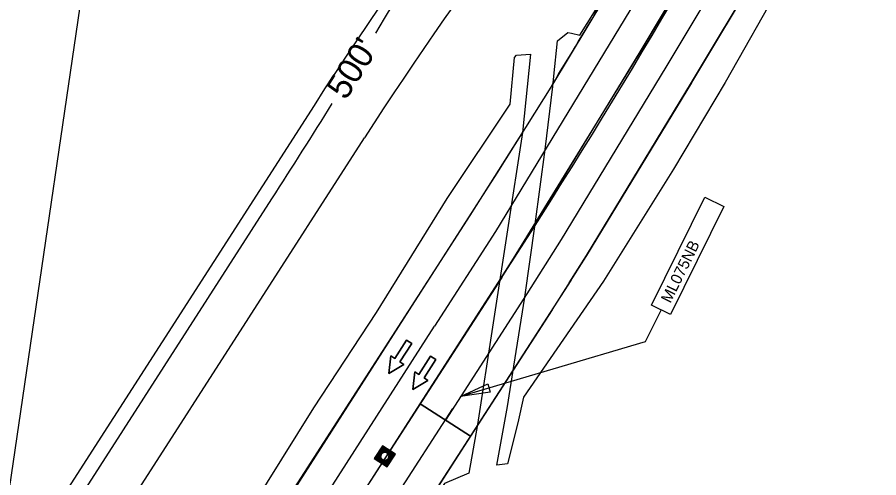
# Model space of a CAD drawing. Extents: x 14104283 to 14128447, y 8633203 to 8671666.
# Drawn here: x 14119316 to 14119660.6, y 8669344.5 to 8669528.4 of the extents above; entities that cross this region are included whole.
import ezdxf

# ---------------------------------------------------------------- set-up
doc = ezdxf.new("R2010")
doc.units = 0
for name, color, linetype in [('dsnCellElements', 7, 'Continuous'), ('dsnNonPlotable', 7, 'Continuous'), ('dsnPaintExistingBrokenLaneLineWhite', 7, 'Continuous'), ('dsnPaintExistingDoubleCenterYellow', 7, 'Continuous'), ('dsnPaintExistingEdgeLineRightWhite', 7, 'Continuous'), ('dsnPaintPlaceBrokenLineWhite', 7, 'Continuous'), ('dsnShadingPaved', 7, 'Continuous'), ('dsnStdLabel', 7, 'Continuous'), ('dsnStgShadingPrevPav', 7, 'Continuous'), ('dsnStgShadingPropPav', 7, 'Continuous'), ('Level 2', 7, 'Continuous'), ('Level 5', 7, 'Continuous'), ('Text', 7, 'Continuous')]:
    doc.layers.add(name, color=color, linetype=linetype)

msp = doc.modelspace()

# ---------------------------------------------------------------- linework, layer by layer
at = {"layer": 'dsnCellElements'}
msp.add_circle((14119463.04, 8669353.02), 1.65, dxfattribs=at)
at = {"layer": 'dsnNonPlotable'}
msp.add_lwpolyline([(14118774.15, 8669147.84), (14119001.66, 8670698.74), (14119501.31, 8670625.45), (14119273.81, 8669074.54)], close=True, dxfattribs=at)
at = {"layer": 'dsnPaintExistingBrokenLaneLineWhite'}
for p, q in [((14119409.98, 8669291.54), (14119482.88, 8669404.98)), ((14119404.97, 8669240.07), (14119490.23, 8669372.15))]:
    msp.add_line(p, q, dxfattribs=at)
msp.add_lwpolyline([(14119581.73, 8669565.18), (14119507.3, 8669442.79), (14119482.88, 8669404.98)], dxfattribs=at)
at = {"layer": 'dsnPaintExistingDoubleCenterYellow'}
for p, q in [((14119494.22, 8669400.39), (14119517.38, 8669436.28)), ((14119403.44, 8669259.76), (14119494.22, 8669400.39))]:
    msp.add_line(p, q, dxfattribs=at)
msp.add_arc((14117116.91, 8670980.36), 2854.2, 327.24958, 332.18395, dxfattribs=at)
at = {"layer": 'dsnPaintExistingEdgeLineRightWhite'}
for p, q in [((14119329.79, 8669101.47), (14119537.52, 8669423.28)), ((14119472.8, 8669411.49), (14119412.15, 8669317.07))]:
    msp.add_line(p, q, dxfattribs=at)
for points in [[(14119571.48, 8669571.41), (14119550.92, 8669536.23), (14119530.04, 8669501.61), (14119507.87, 8669466.11), (14119472.8, 8669411.49)], [(14119536.82, 8669422.39), (14119543.72, 8669433.28), (14119585.72, 8669502.34), (14119612.71, 8669547.49)]]:
    msp.add_lwpolyline(points, dxfattribs=at)
at = {"layer": 'dsnPaintPlaceBrokenLineWhite'}
msp.add_line((14119404.97, 8669240.07), (14119490.23, 8669372.15), dxfattribs=at)
msp.add_lwpolyline([(14119602.41, 8669553.65), (14119575.44, 8669508.54), (14119533.52, 8669439.61), (14119519.81, 8669417.96), (14119487.25, 8669367.53)], dxfattribs=at)
at = {"layer": 'dsnShadingPaved'}
for p, q in [((14119497.21, 8669449.29), (14119518.52, 8669482.93)), ((14119155.5, 8668919.9), (14119497.22, 8669449.29)), ((14119509.78, 8669424.5), (14119403.44, 8669259.76)), ((14119403.44, 8669259.76), (14119477.2, 8669374.02)), ((14119477.17, 8669374.04), (14119497.33, 8669361.02)), ((14119497.33, 8669361.02), (14119415.05, 8669233.56))]:
    msp.add_line(p, q, dxfattribs=at)
for points in [[(14119477.17, 8669374.04), (14119509.75, 8669424.51), (14119523.21, 8669445.75), (14119565.12, 8669514.66), (14119591.92, 8669559.48), (14119612.71, 8669547.49), (14119585.72, 8669502.34), (14119585.63, 8669502.18), (14119543.72, 8669433.28), (14119543.48, 8669432.9), (14119530.02, 8669411.67), (14119529.92, 8669411.5), (14119497.33, 8669361.02), (14119477.17, 8669374.04)], [(14119477.17, 8669374.04), (14119509.75, 8669424.51), (14119523.21, 8669445.75), (14119565.12, 8669514.66), (14119591.92, 8669559.48), (14119612.71, 8669547.49), (14119585.72, 8669502.34), (14119585.63, 8669502.18), (14119543.72, 8669433.28), (14119543.48, 8669432.9), (14119530.02, 8669411.67), (14119529.92, 8669411.5), (14119497.33, 8669361.02), (14119477.17, 8669374.04)], [(14119591.92, 8669559.48), (14119565.12, 8669514.66), (14119509.75, 8669424.51)]]:
    msp.add_lwpolyline(points, dxfattribs=at)
msp.add_arc((14117117.1, 8670980.68), 2830.19, 328.49286, 330.12988, dxfattribs=at)
at = {"layer": 'dsnStdLabel'}
msp.add_line((14119324.41, 8669310.66), (14119417.91, 8669455.95), dxfattribs=at)
for points in [[(14119463.95, 8669348.79), (14119467.27, 8669353.93), (14119462.13, 8669357.26), (14119458.8, 8669352.11), (14119463.95, 8669348.79)], [(14119463.94, 8669348.79), (14119467.27, 8669353.93), (14119462.13, 8669357.25), (14119458.81, 8669352.11), (14119463.95, 8669348.79)], [(14119463.94, 8669348.79), (14119467.26, 8669353.93), (14119462.13, 8669357.25), (14119458.81, 8669352.11), (14119463.95, 8669348.79)], [(14119463.99, 8669348.92), (14119467.22, 8669353.92), (14119462.14, 8669357.2), (14119458.86, 8669352.12), (14119463.97, 8669348.82)], [(14119463.98, 8669348.97), (14119467.17, 8669353.91), (14119462.15, 8669357.16), (14119458.9, 8669352.13), (14119463.99, 8669348.85)], [(14119463.97, 8669349.02), (14119467.13, 8669353.9), (14119462.16, 8669357.11), (14119458.95, 8669352.14), (14119464, 8669348.88)], [(14119463.96, 8669349.06), (14119467.08, 8669353.89), (14119462.17, 8669357.06), (14119458.99, 8669352.15), (14119463.99, 8669348.92)], [(14119463.95, 8669349.11), (14119467.04, 8669353.88), (14119462.18, 8669357.02), (14119459.04, 8669352.16), (14119463.98, 8669348.97)], [(14119463.94, 8669349.15), (14119466.99, 8669353.87), (14119462.19, 8669356.97), (14119459.09, 8669352.17), (14119463.97, 8669349.02)], [(14119463.93, 8669349.2), (14119466.94, 8669353.86), (14119462.2, 8669356.93), (14119459.13, 8669352.18), (14119463.96, 8669349.06)], [(14119463.92, 8669349.24), (14119466.9, 8669353.85), (14119462.21, 8669356.88), (14119459.18, 8669352.19), (14119463.95, 8669349.11)], [(14119463.91, 8669349.29), (14119466.85, 8669353.84), (14119462.22, 8669356.84), (14119459.22, 8669352.2), (14119463.94, 8669349.15)], [(14119463.9, 8669349.34), (14119466.81, 8669353.83), (14119462.23, 8669356.79), (14119459.27, 8669352.21), (14119463.93, 8669349.2)], [(14119463.89, 8669349.38), (14119466.76, 8669353.82), (14119462.24, 8669356.75), (14119459.31, 8669352.22), (14119463.92, 8669349.24)], [(14119463.88, 8669349.43), (14119466.72, 8669353.81), (14119462.25, 8669356.7), (14119459.36, 8669352.23), (14119463.91, 8669349.29)], [(14119463.87, 8669349.47), (14119466.67, 8669353.8), (14119462.26, 8669356.65), (14119459.41, 8669352.24), (14119463.9, 8669349.34)], [(14119463.86, 8669349.52), (14119466.62, 8669353.79), (14119462.27, 8669356.61), (14119459.45, 8669352.25), (14119463.89, 8669349.38)], [(14119463.85, 8669349.56), (14119466.58, 8669353.78), (14119462.28, 8669356.56), (14119459.5, 8669352.26), (14119463.88, 8669349.43)], [(14119463.84, 8669349.61), (14119466.53, 8669353.77), (14119462.29, 8669356.52), (14119459.54, 8669352.27), (14119463.87, 8669349.47)], [(14119463.83, 8669349.65), (14119466.49, 8669353.76), (14119462.3, 8669356.47), (14119459.59, 8669352.28), (14119463.86, 8669349.52)], [(14119463.82, 8669349.7), (14119466.44, 8669353.75), (14119462.31, 8669356.43), (14119459.63, 8669352.29), (14119463.85, 8669349.56)], [(14119463.81, 8669349.75), (14119466.4, 8669353.74), (14119462.32, 8669356.38), (14119459.68, 8669352.3), (14119463.84, 8669349.61)], [(14119463.8, 8669349.79), (14119466.35, 8669353.73), (14119462.33, 8669356.33), (14119459.72, 8669352.31), (14119463.83, 8669349.65)], [(14119463.79, 8669349.84), (14119466.31, 8669353.72), (14119462.34, 8669356.29), (14119459.77, 8669352.32), (14119463.82, 8669349.7)], [(14119463.78, 8669349.88), (14119466.26, 8669353.71), (14119462.35, 8669356.24), (14119459.82, 8669352.33), (14119463.81, 8669349.75)], [(14119463.77, 8669349.93), (14119466.21, 8669353.7), (14119462.36, 8669356.2), (14119459.86, 8669352.34), (14119463.8, 8669349.79)], [(14119463.76, 8669349.97), (14119466.17, 8669353.69), (14119462.37, 8669356.15), (14119459.91, 8669352.35), (14119463.79, 8669349.84)], [(14119463.75, 8669350.02), (14119466.12, 8669353.68), (14119462.37, 8669356.11), (14119459.95, 8669352.36), (14119463.78, 8669349.88)], [(14119463.74, 8669350.07), (14119466.08, 8669353.67), (14119462.38, 8669356.06), (14119460, 8669352.37), (14119463.77, 8669349.93)], [(14119463.73, 8669350.11), (14119466.03, 8669353.67), (14119462.39, 8669356.02), (14119460.04, 8669352.38), (14119463.76, 8669349.97)], [(14119463.72, 8669350.16), (14119465.99, 8669353.66), (14119462.4, 8669355.97), (14119460.09, 8669352.39), (14119463.75, 8669350.02)], [(14119463.72, 8669350.2), (14119465.94, 8669353.65), (14119462.41, 8669355.92), (14119460.14, 8669352.4), (14119463.74, 8669350.07)], [(14119463.71, 8669350.25), (14119465.89, 8669353.64), (14119462.42, 8669355.88), (14119460.18, 8669352.41), (14119463.73, 8669350.11)], [(14119463.7, 8669350.29), (14119465.85, 8669353.63), (14119462.43, 8669355.83), (14119460.23, 8669352.42), (14119463.72, 8669350.16)], [(14119463.69, 8669350.34), (14119465.8, 8669353.62), (14119462.44, 8669355.79), (14119460.27, 8669352.43), (14119463.72, 8669350.2)], [(14119463.68, 8669350.38), (14119465.76, 8669353.61), (14119462.45, 8669355.74), (14119460.32, 8669352.44), (14119463.71, 8669350.25)], [(14119463.67, 8669350.43), (14119465.71, 8669353.6), (14119462.46, 8669355.7), (14119460.36, 8669352.45), (14119463.7, 8669350.29)], [(14119463.66, 8669350.48), (14119465.67, 8669353.59), (14119462.47, 8669355.65), (14119460.41, 8669352.46), (14119463.69, 8669350.34)], [(14119463.65, 8669350.52), (14119465.62, 8669353.58), (14119462.48, 8669355.6), (14119460.45, 8669352.47), (14119463.68, 8669350.38)], [(14119463.64, 8669350.57), (14119465.58, 8669353.57), (14119462.49, 8669355.56), (14119460.5, 8669352.48), (14119463.67, 8669350.43)], [(14119463.63, 8669350.61), (14119465.53, 8669353.56), (14119462.5, 8669355.51), (14119460.55, 8669352.49), (14119463.66, 8669350.48)], [(14119463.62, 8669350.66), (14119465.48, 8669353.55), (14119462.51, 8669355.47), (14119460.59, 8669352.5), (14119463.65, 8669350.52)], [(14119463.61, 8669350.7), (14119465.44, 8669353.54), (14119462.52, 8669355.42), (14119460.64, 8669352.51), (14119463.64, 8669350.57)], [(14119463.6, 8669350.75), (14119465.39, 8669353.53), (14119462.53, 8669355.38), (14119460.68, 8669352.52), (14119463.63, 8669350.61)], [(14119463.59, 8669350.8), (14119465.35, 8669353.52), (14119462.54, 8669355.33), (14119460.73, 8669352.53), (14119463.62, 8669350.66)], [(14119463.58, 8669350.84), (14119465.3, 8669353.51), (14119462.55, 8669355.29), (14119460.77, 8669352.54), (14119463.61, 8669350.7)], [(14119463.65, 8669354.54), (14119462.56, 8669355.24), (14119461.86, 8669354.15)], [(14119463.52, 8669354.58), (14119462.57, 8669355.19), (14119461.96, 8669354.25)], [(14119463.41, 8669354.61), (14119462.58, 8669355.15), (14119462.04, 8669354.32)], [(14119463.32, 8669354.63), (14119462.59, 8669355.1), (14119462.12, 8669354.37)], [(14119463.24, 8669354.64), (14119462.6, 8669355.06), (14119462.19, 8669354.42)], [(14119463.17, 8669354.65), (14119462.61, 8669355.01), (14119462.25, 8669354.45)], [(14119463.1, 8669354.65), (14119462.62, 8669354.97), (14119462.31, 8669354.48)], [(14119463.04, 8669354.66), (14119462.63, 8669354.92), (14119462.36, 8669354.51)], [(14119462.98, 8669354.65), (14119462.64, 8669354.87), (14119462.42, 8669354.53)], [(14119462.92, 8669354.65), (14119462.65, 8669354.83), (14119462.47, 8669354.55)], [(14119462.87, 8669354.65), (14119462.66, 8669354.78), (14119462.52, 8669354.57)], [(14119462.82, 8669354.64), (14119462.67, 8669354.74), (14119462.57, 8669354.59)], [(14119462.77, 8669354.63), (14119462.68, 8669354.69), (14119462.62, 8669354.6)], [(14119462.72, 8669354.62), (14119462.69, 8669354.65), (14119462.67, 8669354.61)], [(14119464.55, 8669352.41), (14119465.26, 8669353.5), (14119464.17, 8669354.2)], [(14119464.6, 8669352.54), (14119465.21, 8669353.49), (14119464.27, 8669354.1)], [(14119464.63, 8669352.65), (14119465.16, 8669353.48), (14119464.33, 8669354.02)], [(14119464.65, 8669352.74), (14119465.12, 8669353.47), (14119464.39, 8669353.94)], [(14119464.66, 8669352.82), (14119465.07, 8669353.46), (14119464.43, 8669353.87)], [(14119461.52, 8669353.63), (14119460.82, 8669352.55), (14119461.91, 8669351.84)], [(14119461.48, 8669353.5), (14119460.87, 8669352.56), (14119461.81, 8669351.94)], [(14119461.45, 8669353.39), (14119460.91, 8669352.56), (14119461.74, 8669352.03)], [(14119461.43, 8669353.31), (14119460.96, 8669352.57), (14119461.69, 8669352.1)], [(14119461.42, 8669353.23), (14119461, 8669352.58), (14119461.64, 8669352.17)], [(14119461.41, 8669353.15), (14119461.05, 8669352.59), (14119461.61, 8669352.23)], [(14119461.41, 8669353.09), (14119461.09, 8669352.6), (14119461.58, 8669352.29)], [(14119461.4, 8669353.02), (14119461.14, 8669352.61), (14119461.55, 8669352.35)], [(14119461.41, 8669352.96), (14119461.18, 8669352.62), (14119461.53, 8669352.4)], [(14119461.41, 8669352.91), (14119461.23, 8669352.63), (14119461.51, 8669352.46)], [(14119461.41, 8669352.85), (14119461.28, 8669352.64), (14119461.49, 8669352.51)], [(14119461.42, 8669352.8), (14119461.32, 8669352.65), (14119461.47, 8669352.56)], [(14119461.43, 8669352.75), (14119461.37, 8669352.66), (14119461.46, 8669352.6)], [(14119461.43, 8669352.71), (14119461.41, 8669352.67), (14119461.45, 8669352.65)], [(14119462.43, 8669351.51), (14119463.6, 8669350.75)], [(14119462.56, 8669351.46), (14119463.59, 8669350.8)], [(14119462.66, 8669351.43), (14119463.58, 8669350.84)], [(14119462.75, 8669351.41), (14119463.57, 8669350.89)], [(14119462.83, 8669351.4), (14119463.56, 8669350.93)], [(14119462.91, 8669351.39), (14119463.55, 8669350.98)], [(14119462.97, 8669351.39), (14119463.54, 8669351.02)], [(14119463.04, 8669351.39), (14119463.53, 8669351.07)], [(14119463.09, 8669351.39), (14119463.52, 8669351.11)], [(14119463.15, 8669351.39), (14119463.51, 8669351.16)], [(14119463.2, 8669351.4), (14119463.5, 8669351.21)], [(14119463.26, 8669351.4), (14119463.49, 8669351.25)], [(14119463.31, 8669351.41), (14119463.48, 8669351.3)], [(14119463.35, 8669351.42), (14119463.47, 8669351.34)], [(14119463.47, 8669351.34), (14119463.55, 8669351.47)], [(14119463.48, 8669351.3), (14119463.6, 8669351.49)], [(14119463.49, 8669351.25), (14119463.66, 8669351.51)], [(14119463.5, 8669351.21), (14119463.71, 8669351.53)], [(14119463.51, 8669351.16), (14119463.77, 8669351.56)], [(14119463.52, 8669351.11), (14119463.83, 8669351.59)], [(14119463.53, 8669351.07), (14119463.89, 8669351.63)], [(14119463.54, 8669351.02), (14119463.96, 8669351.67)], [(14119463.55, 8669350.98), (14119464.03, 8669351.73)], [(14119463.56, 8669350.93), (14119464.11, 8669351.79)], [(14119463.57, 8669350.89), (14119464.22, 8669351.89)], [(14119464.67, 8669352.89), (14119465.03, 8669353.45), (14119464.47, 8669353.81)], [(14119464.67, 8669352.96), (14119464.98, 8669353.44), (14119464.5, 8669353.75)], [(14119464.67, 8669353.02), (14119464.94, 8669353.43), (14119464.53, 8669353.69)], [(14119464.67, 8669353.08), (14119464.89, 8669353.42), (14119464.55, 8669353.64)], [(14119464.67, 8669353.13), (14119464.85, 8669353.41), (14119464.57, 8669353.59)], [(14119464.66, 8669353.19), (14119464.8, 8669353.4), (14119464.59, 8669353.54)], [(14119464.66, 8669353.24), (14119464.75, 8669353.39), (14119464.6, 8669353.49)], [(14119464.65, 8669353.29), (14119464.71, 8669353.38), (14119464.62, 8669353.44)], [(14119464.64, 8669353.34), (14119464.66, 8669353.37), (14119464.63, 8669353.39)]]:
    msp.add_lwpolyline(points, dxfattribs=at)
for start, end in [(328.57258, 335.97179), (327.23683, 328.00604)]:
    msp.add_arc((14116600.71, 8671268.95), 3350.16, start, end, dxfattribs=at)
at = {"layer": 'dsnStgShadingPrevPav'}
for p, q in [((14119540.98, 8669521.24), (14119552.51, 8669539.7)), ((14119530.17, 8669500.82), (14119530.67, 8669504.91)), ((14119518.06, 8669482.38), (14119500.11, 8669365.78)), ((14119512.03, 8669372.94), (14119514.62, 8669389.1))]:
    msp.add_line(p, q, dxfattribs=at)
for points in [[(14119621.71, 8669542.16), (14119599.11, 8669502.43), (14119578.5, 8669467.77), (14119550.51, 8669423.04), (14119518.48, 8669376.61), (14119516.17, 8669366.34), (14119512.13, 8669350.06), (14119507.83, 8669349.42), (14119512.03, 8669372.94)], [(14119530.67, 8669504.91), (14119532.14, 8669518.96), (14119536.17, 8669522.33), (14119537.75, 8669522.14), (14119540.98, 8669521.24)], [(14119513.11, 8669493.72), (14119514.93, 8669512.39), (14119515.74, 8669513.32), (14119521.28, 8669513.76), (14119518.06, 8669482.38)], [(14119514.62, 8669389.1), (14119519.09, 8669416.56), (14119523.21, 8669445.75), (14119527.18, 8669475.65), (14119530.17, 8669500.82)], [(14119403.27, 8669322.21), (14119434.62, 8669372.34), (14119459.73, 8669410.54), (14119488.03, 8669456.05), (14119513.11, 8669493.72)], [(14119500.11, 8669365.78), (14119496.66, 8669346.23), (14119486.9, 8669342.13), (14119480.9, 8669333.22), (14119468.62, 8669311.24), (14119455.82, 8669289.13)]]:
    msp.add_lwpolyline(points, dxfattribs=at)
at = {"layer": 'dsnStgShadingPropPav'}
for p, q in [((14119434.72, 8669493.24), (14119231.48, 8669177.36)), ((14119251.66, 8669164.37), (14119454.9, 8669480.25))]:
    msp.add_line(p, q, dxfattribs=at)
for radius, start in [(1512, 137.73115), (1488, 138.43496)]:
    msp.add_arc((14120706.26, 8668675.12), radius, start, 147.24256, dxfattribs=at)
at = {"layer": 'Level 2'}
for points in [[(14119473.85, 8669398.09), (14119471.75, 8669399.45), (14119467, 8669392.1), (14119465.43, 8669393.11), (14119464.66, 8669386.17), (14119470.68, 8669389.72), (14119469.1, 8669390.74)], [(14119483.47, 8669391.7), (14119481.37, 8669393.05), (14119476.62, 8669385.7), (14119475.05, 8669386.72), (14119474.28, 8669379.77), (14119480.3, 8669383.33), (14119478.72, 8669384.34)]]:
    msp.add_lwpolyline(points, close=True, dxfattribs=at)
at = {"layer": 'Level 5'}
for points in [[(14119469.1, 8669390.74), (14119470.68, 8669389.72), (14119464.66, 8669386.17), (14119465.43, 8669393.11), (14119467, 8669392.1), (14119471.75, 8669399.45), (14119473.85, 8669398.09), (14119469.1, 8669390.74)], [(14119478.72, 8669384.34), (14119480.3, 8669383.33), (14119474.28, 8669379.77), (14119475.05, 8669386.72), (14119476.62, 8669385.7), (14119481.37, 8669393.05), (14119483.47, 8669391.7), (14119478.72, 8669384.34)]]:
    msp.add_lwpolyline(points, dxfattribs=at)
at = {"layer": 'Text'}
for points in [[(14119569.74, 8669413.42), (14119591.07, 8669456.54), (14119598.6, 8669452.82), (14119577.27, 8669409.7)], [(14119569.74, 8669413.42), (14119591.07, 8669456.54), (14119598.6, 8669452.82), (14119577.27, 8669409.7)], [(14119493.34, 8669376.96), (14119504.17, 8669382.01), (14119505.17, 8669378.61)]]:
    msp.add_lwpolyline(points, close=True, dxfattribs=at)
msp.add_lwpolyline([(14119573.51, 8669411.56), (14119567.09, 8669398.77), (14119493.34, 8669376.96)], dxfattribs=at)

# ---------------------------------------------------------------- texts
at = {"layer": 'dsnStdLabel'}
msp.add_text("500'", height=10, rotation=57.6002, dxfattribs=at).set_placement((14119447.43, 8669494.94))
at = {"layer": 'Text'}
msp.add_text('ML075NB', height=4.484, rotation=63.6912, dxfattribs=at).set_placement((14119577.26, 8669413.93))

doc.saveas('drawing.dxf')
